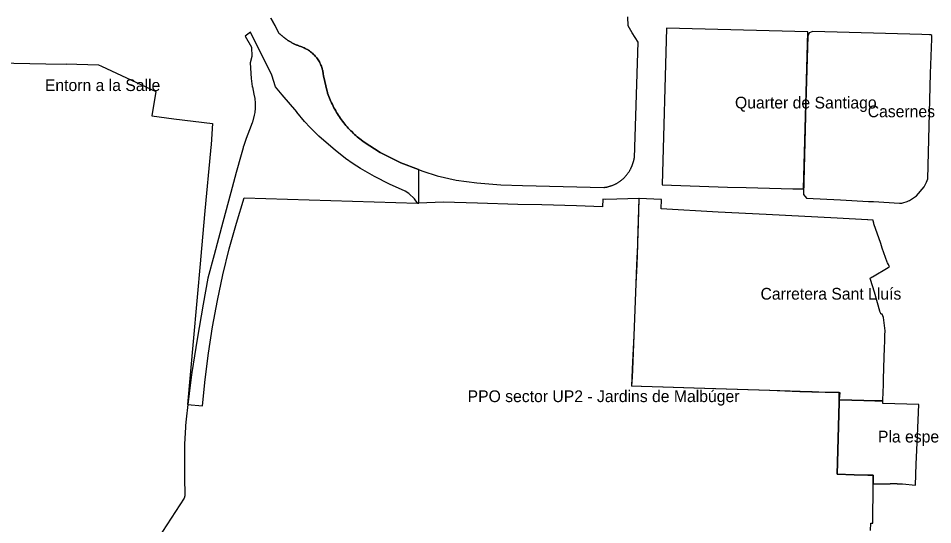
# Model space of a CAD drawing. Extents: x 599912 to 613490, y 4411003 to 4422920.
# Drawn here: x 606785 to 607718, y 4415128 to 4415645 of the extents above; entities that cross this region are included whole.
import ezdxf

# ---------------------------------------------------------------- set-up
doc = ezdxf.new("R2010")
doc.units = 0
for name, color, linetype in [('Límit sòl urbanitzable', 7, 'Continuous'), ('Pla Especial', 7, 'Continuous'), ('Sector amb disposicions transitòries', 7, 'Continuous'), ("Unitat d'Actuació", 7, 'Continuous')]:
    doc.layers.add(name, color=color, linetype=linetype)

msp = doc.modelspace()

# ---------------------------------------------------------------- linework, layer by layer
at = {"layer": 'Límit sòl urbanitzable'}
msp.add_lwpolyline([(607042.51, 4415645.65), (607046.68, 4415637.75), (607050.72, 4415630.26), (607051.34, 4415629.65), (607051.96, 4415629.05), (607052.6, 4415628.46), (607053.24, 4415627.88), (607053.9, 4415627.3), (607054.56, 4415626.74), (607055.23, 4415626.19), (607055.91, 4415625.65), (607056.59, 4415625.12), (607057.01, 4415624.8), (607057.28, 4415624.6), (607057.99, 4415624.08), (607058.69, 4415623.58), (607059.41, 4415623.09), (607059.76, 4415622.86), (607060.43, 4415622.44), (607060.48, 4415622.41), (607060.76, 4415622.23), (607060.79, 4415622.22), (607061.1, 4415622.03), (607061.78, 4415621.62), (607062.46, 4415621.23), (607063.14, 4415620.84), (607063.84, 4415620.47), (607064.53, 4415620.1), (607065.23, 4415619.74), (607065.94, 4415619.39), (607066.12, 4415619.31), (607066.13, 4415619.3), (607066.65, 4415619.05), (607067.36, 4415618.72), (607068.08, 4415618.4), (607068.8, 4415618.09), (607069.53, 4415617.78), (607070.26, 4415617.49), (607071, 4415617.2), (607071.73, 4415616.93), (607072.93, 4415616.55), (607074.11, 4415616.13), (607075.28, 4415615.66), (607076.25, 4415615.24), (607076.31, 4415615.21), (607076.43, 4415615.15), (607077.56, 4415614.6), (607078.67, 4415614.01), (607079.75, 4415613.38), (607080.49, 4415612.91), (607080.6, 4415612.85), (607080.82, 4415612.71), (607081.85, 4415612), (607082.69, 4415611.38), (607082.86, 4415611.25), (607083.84, 4415610.47), (607084.38, 4415610.01), (607084.49, 4415609.91), (607084.8, 4415609.65), (607085.72, 4415608.79), (607085.91, 4415608.6), (607086.61, 4415607.91), (607086.63, 4415607.88), (607086.78, 4415607.73), (607087.62, 4415606.83), (607088.42, 4415605.89), (607089.19, 4415604.93), (607089.92, 4415603.94), (607090.62, 4415602.92), (607091.28, 4415601.88), (607091.89, 4415600.82), (607092.47, 4415599.73), (607093.01, 4415598.62), (607093.5, 4415597.49), (607093.96, 4415596.35), (607094.37, 4415595.18), (607094.38, 4415595.13), (607094.42, 4415595.02), (607094.73, 4415594.01), (607094.76, 4415593.92), (607094.86, 4415593.54), (607095.05, 4415592.82), (607095.33, 4415591.62), (607095.56, 4415590.41), (607095.63, 4415589.95), (607095.75, 4415589.19), (607095.89, 4415587.97), (607096.06, 4415587.24), (607096.24, 4415586.48), (607099.9, 4415570.71), (607100.09, 4415569.89), (607100.29, 4415569.03), (607100.9, 4415567.32), (607101.53, 4415565.61), (607102.19, 4415563.91), (607102.89, 4415562.23), (607103.61, 4415560.56), (607104.36, 4415558.91), (607105.15, 4415557.26), (607105.96, 4415555.63), (607106.8, 4415554.02), (607107.67, 4415552.42), (607108.57, 4415550.84), (607109.49, 4415549.27), (607110.45, 4415547.72), (607111.43, 4415546.19), (607112.44, 4415544.68), (607113.48, 4415543.18), (607114.54, 4415541.7), (607115.63, 4415540.24), (607116.74, 4415538.8), (607117.88, 4415537.39), (607119.05, 4415535.99), (607120.24, 4415534.61), (607121.45, 4415533.26), (607122.69, 4415531.92), (607123.95, 4415530.61), (607125.24, 4415529.32), (607126.55, 4415528.06), (607127.88, 4415526.82), (607129.23, 4415525.6), (607130.61, 4415524.41), (607132, 4415523.24), (607137.75, 4415518.93), (607154, 4415508.47), (607175.11, 4415497.65), (607193.04, 4415490.82), (607197.4, 4415489.16), (607212.05, 4415484.56), (607231.34, 4415480.24), (607252.44, 4415477.26), (607277.07, 4415475.31), (607299.02, 4415474.52), (607382.07, 4415472.64), (607382.67, 4415472.71), (607383.26, 4415472.79), (607383.86, 4415472.89), (607384.45, 4415472.99), (607385.04, 4415473.1), (607385.62, 4415473.23), (607386.21, 4415473.36), (607386.79, 4415473.5), (607387.37, 4415473.65), (607387.95, 4415473.81), (607388.53, 4415473.98), (607389.1, 4415474.17), (607389.67, 4415474.36), (607390.23, 4415474.56), (607390.8, 4415474.76), (607391.35, 4415474.98), (607391.91, 4415475.21), (607392.46, 4415475.45), (607393.01, 4415475.69), (607393.55, 4415475.95), (607394.09, 4415476.21), (607394.62, 4415476.49), (607395.15, 4415476.77), (607395.68, 4415477.06), (607396.2, 4415477.36), (607396.71, 4415477.67), (607397.22, 4415477.98), (607397.73, 4415478.31), (607398.23, 4415478.64), (607398.72, 4415478.98), (607399.21, 4415479.33), (607399.64, 4415479.66), (607400.06, 4415480), (607400.48, 4415480.34), (607400.9, 4415480.69), (607401.31, 4415481.05), (607401.71, 4415481.41), (607402.11, 4415481.78), (607402.5, 4415482.15), (607402.89, 4415482.53), (607403.27, 4415482.92), (607403.65, 4415483.31), (607404.02, 4415483.71), (607404.38, 4415484.11), (607404.74, 4415484.52), (607405.09, 4415484.93), (607405.43, 4415485.35), (607405.77, 4415485.78), (607406.1, 4415486.21), (607406.43, 4415486.64), (607406.75, 4415487.08), (607407.06, 4415487.52), (607407.37, 4415487.97), (607407.66, 4415488.42), (607407.96, 4415488.88), (607408.24, 4415489.34), (607408.52, 4415489.81), (607408.79, 4415490.28), (607409.05, 4415490.75), (607409.31, 4415491.23), (607409.56, 4415491.72), (607409.8, 4415492.2), (607409.94, 4415492.53), (607410.08, 4415492.86), (607410.23, 4415493.19), (607410.36, 4415493.52), (607410.5, 4415493.85), (607410.63, 4415494.19), (607410.77, 4415494.52), (607410.9, 4415494.86), (607411.02, 4415495.19), (607411.15, 4415495.53), (607411.27, 4415495.87), (607411.39, 4415496.21), (607411.51, 4415496.54), (607411.63, 4415496.88), (607411.74, 4415497.22), (607411.86, 4415497.57), (607411.97, 4415497.91), (607412.07, 4415498.25), (607412.18, 4415498.59), (607412.28, 4415498.94), (607412.38, 4415499.28), (607412.48, 4415499.63), (607412.58, 4415499.97), (607412.68, 4415500.32), (607412.77, 4415500.67), (607412.86, 4415501.02), (607412.95, 4415501.36), (607413.03, 4415501.71), (607413.12, 4415502.06), (607413.2, 4415502.41), (607413.28, 4415502.76), (607417.32, 4415620.95), (607411.05, 4415630.54), (607406.81, 4415637.76), (607406.62, 4415647.01)], dxfattribs=at)
msp.add_lwpolyline([(607667.12, 4415264.23), (607667.32, 4415270.49), (607667.5, 4415276.25), (607667.9, 4415288.78), (607668.21, 4415298.84), (607668.3, 4415301.72), (607668.45, 4415306.31), (607668.83, 4415318.32), (607668.83, 4415318.33), (607668.94, 4415321.81), (607669.08, 4415326.38), (607667.32, 4415339.8), (607665.95, 4415343.35), (607665.55, 4415343.42), (607664.75, 4415343.56), (607664.59, 4415343.97), (607663.82, 4415345.85), (607663.67, 4415346.13), (607663.61, 4415346.25), (607658.12, 4415365.84), (607654.21, 4415378.67), (607653.82, 4415379.96), (607653.79, 4415380.06), (607655.85, 4415381.26), (607656.14, 4415381.43), (607672.31, 4415391.03), (607673.51, 4415391.75), (607672.41, 4415393.93), (607672.41, 4415393.95), (607671.53, 4415395.7), (607671.21, 4415396.34), (607666.27, 4415410.69), (607664.63, 4415415.44), (607657.68, 4415435.6), (607657.48, 4415436.18), (607657.03, 4415438.46), (607656.85, 4415439.37), (607651.64, 4415439.65), (607651.31, 4415439.66), (607620.23, 4415441.23), (607547.6, 4415445.05), (607498.84, 4415447.59), (607440.74, 4415450.85), (607441.13, 4415460.2), (607417.98, 4415461.51), (607417.57, 4415448.21), (607416.86, 4415425.02), (607416.63, 4415417.23), (607416.55, 4415413.92), (607415.64, 4415393.82), (607414.9, 4415374.74), (607412.68, 4415321.38), (607411.59, 4415294.92), (607410.9, 4415278.97), (607410.52, 4415270.02), (607420.14, 4415269.72), (607442.48, 4415269.04), (607474.01, 4415268.05), (607551.24, 4415265.53), (607582.17, 4415264.4), (607587.48, 4415264.24), (607594.22, 4415264.04), (607608.06, 4415263.66), (607611.33, 4415263.58), (607622.94, 4415263.31), (607622.31, 4415255.99), (607622.84, 4415255.97), (607622.86, 4415255.97), (607647.5, 4415255.27), (607658.71, 4415254.95), (607666.82, 4415254.73)], close=True, dxfattribs=at)
at = {"layer": 'Pla Especial'}
msp.add_lwpolyline([(606763.67, 4415599.97), (606812.71, 4415599), (606833.49, 4415598.59), (606833.52, 4415598.71), (606866.64, 4415597.76), (606869.55, 4415596.54), (606924.91, 4415570.72), (606921.09, 4415545.94), (606943.56, 4415542.64), (606982.94, 4415537.9), (606981.37, 4415516.57), (606980.92, 4415510.37), (606980.73, 4415509.9), (606975.05, 4415448.83), (606970.6, 4415398.69), (606970.59, 4415398.58), (606963.19, 4415315.31), (606957.47, 4415250.96), (606972.58, 4415249.58), (606975.26, 4415276.6), (606978.71, 4415303.54), (606982.91, 4415330.36), (606987.87, 4415357.06), (606993.58, 4415383.6), (607000.04, 4415409.98), (607007.24, 4415436.16), (607015.18, 4415462.12), (607192.13, 4415456.7), (607193.28, 4415456.75), (607193.34, 4415490.63), (607193.04, 4415490.82), (607175.11, 4415497.65), (607154, 4415508.47), (607137.75, 4415518.93), (607132, 4415523.24), (607130.61, 4415524.41), (607129.23, 4415525.6), (607127.88, 4415526.82), (607126.55, 4415528.06), (607125.24, 4415529.32), (607123.95, 4415530.61), (607122.69, 4415531.92), (607121.45, 4415533.26), (607120.24, 4415534.61), (607119.05, 4415535.99), (607117.88, 4415537.39), (607116.74, 4415538.8), (607115.63, 4415540.24), (607114.54, 4415541.7), (607113.48, 4415543.18), (607112.44, 4415544.68), (607111.43, 4415546.19), (607110.45, 4415547.72), (607109.49, 4415549.27), (607108.57, 4415550.84), (607107.67, 4415552.42), (607106.8, 4415554.02), (607105.96, 4415555.63), (607105.15, 4415557.26), (607104.36, 4415558.91), (607103.61, 4415560.56), (607102.89, 4415562.23), (607102.19, 4415563.91), (607101.53, 4415565.61), (607100.9, 4415567.32), (607100.29, 4415569.03), (607100.09, 4415569.89), (607099.9, 4415570.71), (607096.24, 4415586.48), (607096.06, 4415587.24), (607095.89, 4415587.97), (607095.75, 4415589.19), (607095.63, 4415589.95), (607095.56, 4415590.41), (607095.33, 4415591.62), (607095.05, 4415592.82), (607094.86, 4415593.54), (607094.76, 4415593.92), (607094.73, 4415594.01), (607094.42, 4415595.02), (607094.38, 4415595.13), (607094.37, 4415595.18), (607093.96, 4415596.35), (607093.5, 4415597.49), (607093.01, 4415598.62), (607092.47, 4415599.73), (607091.89, 4415600.82), (607091.28, 4415601.88), (607090.62, 4415602.92), (607089.92, 4415603.94), (607089.19, 4415604.93), (607088.42, 4415605.89), (607087.62, 4415606.83), (607086.78, 4415607.73), (607086.63, 4415607.88), (607086.61, 4415607.91), (607085.91, 4415608.6), (607085.72, 4415608.79), (607084.8, 4415609.65), (607084.49, 4415609.91), (607084.38, 4415610.01), (607083.84, 4415610.47), (607082.86, 4415611.25), (607081.85, 4415612), (607080.82, 4415612.71), (607080.6, 4415612.85), (607080.49, 4415612.91), (607079.75, 4415613.38), (607078.67, 4415614.01), (607077.56, 4415614.6), (607076.43, 4415615.15), (607076.31, 4415615.21), (607076.25, 4415615.24), (607075.28, 4415615.66), (607074.11, 4415616.13), (607072.93, 4415616.55), (607071.73, 4415616.93), (607071, 4415617.2), (607070.26, 4415617.49), (607069.53, 4415617.78), (607068.8, 4415618.09), (607068.08, 4415618.4), (607067.36, 4415618.72), (607066.65, 4415619.05), (607066.13, 4415619.3), (607066.12, 4415619.31), (607065.94, 4415619.39), (607065.23, 4415619.74), (607064.53, 4415620.1), (607063.84, 4415620.47), (607063.14, 4415620.84), (607062.46, 4415621.23), (607061.78, 4415621.62), (607061.1, 4415622.03), (607060.79, 4415622.22), (607060.76, 4415622.23), (607060.43, 4415622.44), (607059.76, 4415622.86), (607059.41, 4415623.09), (607058.69, 4415623.58), (607057.99, 4415624.08), (607057.28, 4415624.6), (607057.01, 4415624.8), (607056.59, 4415625.12), (607055.91, 4415625.65), (607055.23, 4415626.19), (607054.56, 4415626.74), (607053.9, 4415627.3), (607053.24, 4415627.88), (607052.6, 4415628.46), (607051.96, 4415629.05), (607051.34, 4415629.65), (607050.72, 4415630.26), (607046.68, 4415637.75), (607042.51, 4415645.65)], dxfattribs=at)
at = {"layer": 'Sector amb disposicions transitòries'}
msp.add_lwpolyline([(607654.36, 4415122.56), (607654.57, 4415129.76), (607656.43, 4415129.72), (607656.91, 4415169.85), (607656.91, 4415169.94), (607656.98, 4415178.68), (607656.98, 4415178.76), (607656.68, 4415178.76), (607651.4, 4415178.84), (607637.49, 4415179.33), (607620.3, 4415179.8), (607620.25, 4415179.8), (607622.35, 4415252.96), (607622.23, 4415263.13), (607611.64, 4415263.38), (607608.36, 4415263.45), (607594.53, 4415263.84), (607587.79, 4415264.04), (607582.48, 4415264.19), (607551.55, 4415265.33), (607474.32, 4415267.85), (607442.78, 4415268.84), (607420.44, 4415269.52), (607410.83, 4415269.82), (607411.2, 4415278.77), (607411.89, 4415294.72), (607412.99, 4415321.18), (607415.2, 4415374.54), (607415.95, 4415393.62), (607416.85, 4415413.72), (607416.93, 4415417.03), (607418.28, 4415461.31), (607383.97, 4415460.47), (607381.06, 4415460.62), (607380.7, 4415453.03), (607354.08, 4415453.86), (607318.79, 4415454.86), (607294.54, 4415455.34), (607253.39, 4415456.71), (607218.1, 4415457.72), (607193.28, 4415456.75), (607192.13, 4415456.7), (607188.92, 4415461.06), (607183.18, 4415466.52), (607179.48, 4415469), (607163.53, 4415476.02), (607148.04, 4415483.77), (607133.81, 4415492), (607126.26, 4415496.79), (607118.46, 4415502.3), (607108.02, 4415510.65), (607098.78, 4415518.43), (607091.36, 4415525.08), (607082.69, 4415533.72), (607076.63, 4415540.14), (607069.06, 4415549.62), (607068.75, 4415549.81), (607053.88, 4415567.17), (607046.99, 4415575.52), (607043.39, 4415587.22), (607021.75, 4415631.18), (607016.3, 4415627.12), (607022.6, 4415616.02), (607022.66, 4415615.92), (607022.67, 4415615.84), (607022.96, 4415606.33), (607021.26, 4415599.76), (607022.16, 4415583.91), (607023.25, 4415575.6), (607023.28, 4415575.18), (607023.3, 4415575.18), (607023.6, 4415575.25), (607023.61, 4415575.25), (607025.18, 4415567.95), (607025.93, 4415563.47), (607026.51, 4415558.83), (607026.55, 4415556.77), (607026.4, 4415553.5), (607025.98, 4415549.32), (607025.35, 4415546.63), (607023.67, 4415539.42), (607023.43, 4415538.77), (607020.72, 4415531.44), (607017.34, 4415522.5), (607014.84, 4415515.35), (607014.31, 4415513.82), (607014.06, 4415513.1), (607012.09, 4415505.87), (607007.1, 4415487.99), (607007.05, 4415487.8), (607001.52, 4415467.61), (606993.46, 4415437.15), (606984.62, 4415403.91), (606984.62, 4415403.91), (606984.56, 4415403.7), (606978.25, 4415379.91), (606973.24, 4415353.64), (606973.22, 4415353.57), (606967.34, 4415317.91), (606961.72, 4415283.85), (606961.3, 4415281.3), (606960.67, 4415276.26), (606957.56, 4415251.12), (606956, 4415236.22), (606955.3, 4415229.53), (606955.21, 4415227.74), (606954.38, 4415210.4), (606954.38, 4415210.4), (606954.42, 4415204.44), (606954.33, 4415177.09), (606954.59, 4415157.7), (606954.1, 4415155.42), (606918.47, 4415100.94)], dxfattribs=at)
for points in [[(607590.35, 4415631.42), (607446.08, 4415635.42), (607441.54, 4415475.23), (607508.42, 4415473.05), (607527.27, 4415472.51), (607574.92, 4415471.16), (607585.96, 4415471.13)], [(607702.22, 4415219.15), (607703.37, 4415251.07), (607703.37, 4415251.15), (607666.73, 4415251.97), (607666.82, 4415254.73), (607658.71, 4415254.95), (607647.5, 4415255.27), (607622.86, 4415255.97), (607622.31, 4415255.99), (607622.35, 4415252.96), (607620.25, 4415179.8), (607637.49, 4415179.33), (607651.4, 4415178.84), (607656.68, 4415178.76), (607656.98, 4415178.76), (607656.98, 4415178.68), (607656.91, 4415169.94), (607674.43, 4415170.1), (607674.42, 4415170.46), (607681.26, 4415170.55), (607681.27, 4415170.29), (607681.28, 4415170.1), (607686.79, 4415170.02), (607700.25, 4415168.56), (607700.94, 4415190.13)]]:
    msp.add_lwpolyline(points, close=True, dxfattribs=at)
at = {"layer": "Unitat d'Actuació"}
msp.add_lwpolyline([(607686.08, 4415456.78), (607692.65, 4415458.81), (607692.72, 4415458.83), (607693.88, 4415459.19), (607701.02, 4415463.99), (607708.8, 4415473.39), (607711.41, 4415478.15), (607712.54, 4415481.58), (607715.53, 4415588.94), (607716.81, 4415624.47), (607716.86, 4415625.89), (607716.89, 4415627.76), (607715.64, 4415628.59), (607714.56, 4415628.62), (607706.5, 4415628.81), (607595.22, 4415631.94), (607591.58, 4415630.58), (607590.23, 4415627.23), (607588.29, 4415558.85), (607585.81, 4415465.49), (607588.89, 4415461.74), (607623.44, 4415459.95), (607652.01, 4415458.47), (607657.11, 4415458.21), (607683.7, 4415456.76)], close=True, dxfattribs=at)

# ---------------------------------------------------------------- texts
at = {"layer": 'Límit sòl urbanitzable'}
msp.add_text('Carretera Sant Lluís', height=12, dxfattribs=at).set_placement((607542.02, 4415358.12))
at = {"layer": 'Pla Especial'}
msp.add_text('Entorn a la Salle', height=12, dxfattribs=at).set_placement((606811.87, 4415571.09))
at = {"layer": 'Sector amb disposicions transitòries'}
for s, p in [('Quarter de Santiago', (607515.94, 4415553.28)), ('PPO sector UP2 - Jardins de Malbúger', (607243.15, 4415253.48)), ("Pla especial de ref.  interior 'Villa Luisa'", (607661.81, 4415212.27))]:
    msp.add_text(s, height=12, dxfattribs=at).set_placement(p)
at = {"layer": "Unitat d'Actuació"}
msp.add_text('Casernes de Santiago', height=12, dxfattribs=at).set_placement((607651.35, 4415544.35))

doc.saveas('drawing.dxf')
